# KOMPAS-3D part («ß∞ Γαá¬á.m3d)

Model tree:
1. Эскиз:1
2. Операция выдавливания:1
     Расстояние 1 = 34.5; Расстояние 2 = 1
3. Эскиз:2
4. Операция выдавливания:2
     Расстояние 1 = 0.1; Расстояние 2 = 1
5. Скругление:1
     Радиус = 0.1
6. Скругление:2
     Радиус = 0.1
